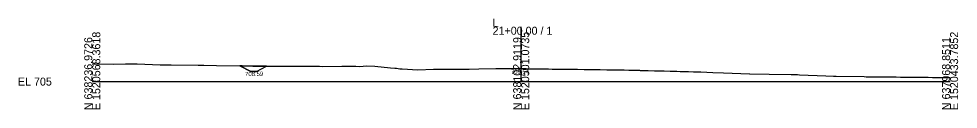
# Model space of a CAD drawing. Extents: x -26 to 3903, y -10 to 9531.
# Drawn here: x 974.3 to 1302.8, y 990.3 to 1022 of the extents above; entities that cross this region are included whole.
import ezdxf

# ---------------------------------------------------------------- set-up
doc = ezdxf.new("R2010")
doc.units = 0
for name, color, linetype in [('Default', 7, 'Continuous'), ('Exist Cross Section Cell', 7, 'Continuous'), ('Exist XS Center Line Elevation Label', 7, 'Continuous'), ('Exist XS Ground Line', 7, 'Continuous'), ('Prop XS DDE', 7, 'Continuous'), ('Prop XS DDE Earthwork Shape', 7, 'Continuous'), ('Prop XS DDE Elevations', 7, 'Continuous')]:
    doc.layers.add(name, color=color, linetype=linetype)

msp = doc.modelspace()

# ---------------------------------------------------------------- linework, layer by layer
at = {"layer": 'Exist Cross Section Cell'}
for p, q in [((1150, 1000), (1150, 1019.24)), ((1000, 1000), (1150, 1000)), ((1150, 1000), (1300, 1000))]:
    msp.add_line(p, q, dxfattribs=at)
at = {"layer": 'Exist XS Ground Line'}
msp.add_lwpolyline([(1000, 1006.18), (1007.47, 1006.15), (1011.62, 1006.21), (1015.75, 1006.2), (1023.7, 1005.92), (1027.63, 1005.86), (1036.99, 1005.78), (1039.02, 1005.78), (1043.42, 1005.68), (1052.43, 1005.48), (1056.14, 1005.41), (1058.78, 1005.39), (1069.74, 1005.37), (1075.27, 1005.44), (1079.51, 1005.36), (1080.65, 1005.35), (1087.28, 1005.45), (1089.54, 1005.38), (1092.2, 1005.36), (1093.53, 1005.35), (1095.92, 1005.5), (1098.8, 1005.46), (1104.35, 1004.83), (1105.87, 1004.73), (1106.38, 1004.73), (1107.56, 1004.51), (1108.38, 1004.44), (1113.86, 1004.08), (1119.3, 1004.35), (1125.76, 1004.32), (1128.01, 1004.35), (1131.84, 1004.41), (1135.2, 1004.47), (1141.09, 1004.56), (1144.03, 1004.61), (1144.93, 1004.6), (1147.22, 1004.58), (1148.29, 1004.56), (1149.32, 1004.55), (1150.26, 1004.54), (1151.69, 1004.54), (1152.25, 1004.53), (1152.7, 1004.53), (1153.62, 1004.51), (1154.89, 1004.49), (1155.81, 1004.48), (1156.27, 1004.48), (1157.64, 1004.46), (1159.07, 1004.45), (1159.61, 1004.44), (1160.83, 1004.42), (1161.63, 1004.41), (1163.25, 1004.39), (1163.51, 1004.39), (1163.63, 1004.39), (1164.01, 1004.39), (1166.42, 1004.35), (1167.22, 1004.34), (1168.8, 1004.32), (1169.09, 1004.32), (1169.23, 1004.31), (1169.66, 1004.31), (1172.02, 1004.27), (1172.8, 1004.27), (1174.35, 1004.25), (1174.82, 1004.24), (1176.52, 1004.22), (1177.61, 1004.2), (1179.9, 1004.18), (1180.22, 1004.18), (1180.54, 1004.17), (1181.59, 1004.17), (1182.45, 1004.16), (1183.52, 1004.13), (1185.44, 1004.08), (1185.81, 1004.07), (1186, 1004.07), (1187.69, 1004.04), (1188.81, 1004.01), (1191.02, 1003.97), (1191.41, 1003.96), (1191.61, 1003.95), (1193.28, 1003.91), (1194.4, 1003.89), (1196.62, 1003.83), (1197, 1003.82), (1197.2, 1003.82), (1197.78, 1003.8), (1199.99, 1003.74), (1202.15, 1003.69), (1202.58, 1003.68), (1202.79, 1003.67), (1204.46, 1003.62), (1205.6, 1003.6), (1207.74, 1003.54), (1208.54, 1003.52), (1210.23, 1003.47), (1210.92, 1003.45), (1212.35, 1003.41), (1212.85, 1003.4), (1217.06, 1003.21), (1220.74, 1003.05), (1229.83, 1002.7), (1229.88, 1002.7), (1229.96, 1002.7), (1236.71, 1002.6), (1244.41, 1002.5), (1246.13, 1002.46), (1246.67, 1002.45), (1247.3, 1002.43), (1256.5, 1002.08), (1259.28, 1001.96), (1259.57, 1001.96), (1259.81, 1001.95), (1260.17, 1001.95), (1269.96, 1001.75), (1270.64, 1001.73), (1273.23, 1001.71), (1274.72, 1001.69), (1275.26, 1001.69), (1275.53, 1001.69), (1276.34, 1001.68), (1278.32, 1001.65), (1280.25, 1001.63), (1280.82, 1001.63), (1281.11, 1001.62), (1282.69, 1001.61), (1283.91, 1001.6), (1285.83, 1001.58), (1286.71, 1001.57), (1287.61, 1001.56), (1289.5, 1001.53), (1291.36, 1001.51), (1291.99, 1001.51), (1292.3, 1001.5), (1293.86, 1001.49), (1295.1, 1001.47), (1295.72, 1001.46), (1296.94, 1001.45), (1297.42, 1001.44), (1298.04, 1001.44), (1298.87, 1001.43), (1299.65, 1001.42), (1300, 1001.41)], dxfattribs=at)
at = {"layer": 'Prop XS DDE'}
for p, q in [((1055.4, 1003.59), (1051.58, 1005.5)), ((1057.4, 1003.59), (1060.99, 1005.39)), ((1057.4, 1003.59), (1055.4, 1003.59))]:
    msp.add_line(p, q, dxfattribs=at)
at = {"layer": 'Prop XS DDE Earthwork Shape'}
for p, q in [((1051.58, 1005.5), (1055.4, 1003.59)), ((1057.4, 1003.59), (1060.99, 1005.39)), ((1060.99, 1005.39), (1058.78, 1005.39)), ((1055.4, 1003.59), (1057.4, 1003.59))]:
    msp.add_line(p, q, dxfattribs=at)
msp.add_lwpolyline([(1058.78, 1005.39), (1056.14, 1005.41), (1052.43, 1005.48), (1051.58, 1005.5)], dxfattribs=at)

# ---------------------------------------------------------------- texts
at = {"layer": 'Default'}
msp.add_text('-', height=0.0001, dxfattribs=at).set_placement((1000, 1000))
at = {"layer": 'Exist Cross Section Cell'}
for s, p in [('L', (1140, 1019.24)), ('21+00.00 / 1', (1140, 1016.44)), ('EL 705', (974, 998.6))]:
    msp.add_text(s, height=2.8, dxfattribs=at).set_placement(p)
for s, p in [('N 638236.9726', (1000, 990)), ('E 1520568.3618', (1002.8, 990)), ('N 638102.9119', (1150, 990)), ('E 1520501.0735', (1152.8, 990)), ('N 637968.8511', (1300, 990)), ('E 1520433.7852', (1302.8, 990))]:
    msp.add_text(s, height=2.8, rotation=90, dxfattribs=at).set_placement(p)
at = {"layer": 'Exist XS Center Line Elevation Label'}
msp.add_text('709.54', height=1.5, rotation=0.8401, dxfattribs=at).set_placement((1146.42, 1002.71))
at = {"layer": 'Prop XS DDE Elevations'}
msp.add_text('708.59', height=1.5, rotation=0.8401, dxfattribs=at).set_placement((1053.46, 1001.91))

doc.saveas('drawing.dxf')
